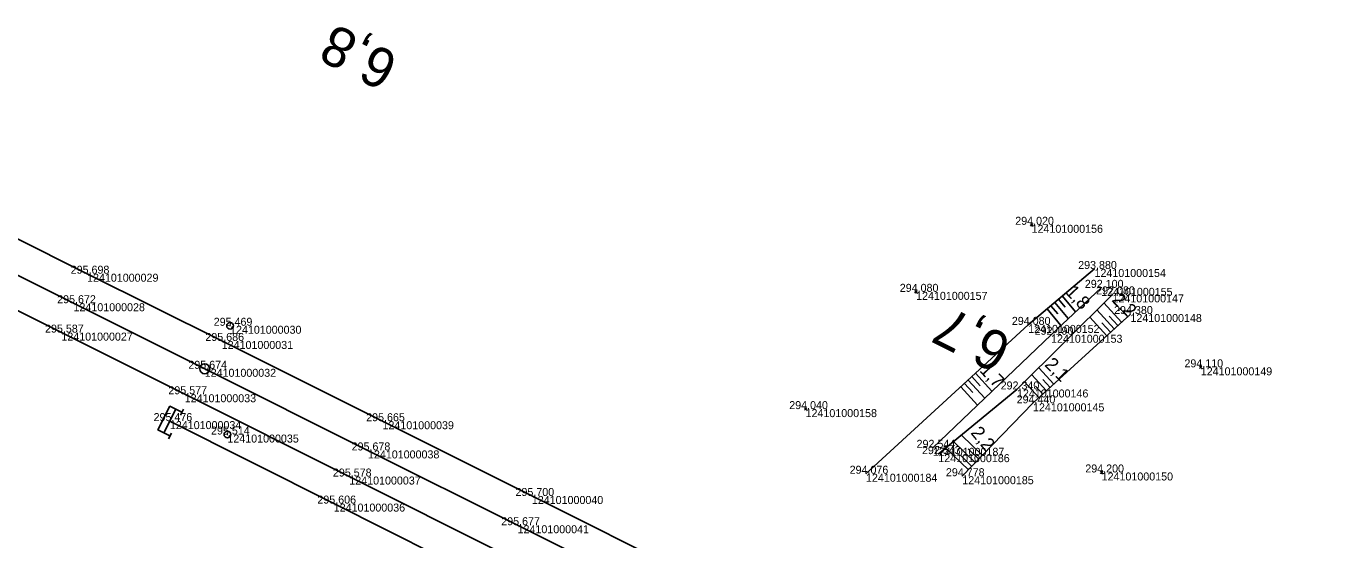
# Model space of a CAD drawing. Extents: x -616949 to -607976, y -1164436 to -1159224.
# Drawn here: x -613176.1 to -612978.5, y -1161592 to -1161515 of the extents above; entities that cross this region are included whole.
import ezdxf

# ---------------------------------------------------------------- set-up
doc = ezdxf.new("R2010")
doc.units = 0
for name, color, linetype in [('Vrstva 1', 7, 'Continuous'), ('Vrstva 15', 7, 'Continuous'), ('Vrstva 48', 7, 'Continuous'), ('Vrstva 49', 7, 'Continuous'), ('Vrstva 53', 7, 'Continuous'), ('Vrstva 60', 7, 'Continuous'), ('Vrstva 61', 7, 'Continuous'), ('Vrstva 7', 7, 'Continuous')]:
    doc.layers.add(name, color=color, linetype=linetype)

msp = doc.modelspace()

# ---------------------------------------------------------------- linework, layer by layer
at = {"layer": 'Vrstva 1'}
for points in [[(-612836.3, -1161723.7), (-612837.64, -1161723.01), (-612851, -1161716.12), (-612864.8, -1161706.96), (-612874.11, -1161700.74), (-612883.8, -1161694.67), (-612893.99, -1161688.92), (-612900.94, -1161685.35), (-612902.32, -1161684.67), (-612923.96, -1161673.82), (-612946.7, -1161662.43), (-612968.71, -1161651.4), (-612992.18, -1161639.63), (-613014.55, -1161628.42), (-613038.93, -1161616.22), (-613057.44, -1161606.93), (-613076.92, -1161597.16), (-613100.26, -1161585.47), (-613122.66, -1161574.25), (-613146.78, -1161562.2), (-613166.98, -1161552.11), (-613189.63, -1161540.79)], [(-612836.3, -1161723.7), (-612837.64, -1161723.01), (-612851, -1161716.12), (-612865.7, -1161708.54), (-612879.87, -1161701.29), (-612896.11, -1161693.08), (-612897.16, -1161692.56), (-612899.6, -1161691.36), (-612902.62, -1161689.84), (-612904.01, -1161689.16), (-612926.34, -1161677.97), (-612949.01, -1161666.64), (-612970.85, -1161655.69), (-612994.2, -1161644.02), (-613016.8, -1161632.71), (-613041.11, -1161620.53), (-613059.39, -1161611.38), (-613079.39, -1161601.37), (-613102.4, -1161589.86), (-613124.84, -1161578.63), (-613149.33, -1161566.38), (-613169.01, -1161556.54), (-613191.83, -1161545.12)], [(-612838.4, -1161727.97), (-612839.52, -1161727.39), (-612849.62, -1161722.19), (-612861.87, -1161715.89), (-612876.82, -1161708.21), (-612890.37, -1161701.36), (-612894.8, -1161699.12), (-612896.29, -1161698.37), (-612899.37, -1161696.83), (-612901.81, -1161695.62), (-612928.78, -1161682.13), (-612951.31, -1161670.85), (-612973.15, -1161659.9), (-612996.39, -1161648.28), (-613019.15, -1161636.88), (-613042.98, -1161624.98), (-613061.36, -1161615.73), (-613081.95, -1161605.44), (-613104.41, -1161594.19), (-613127.64, -1161582.55), (-613152.33, -1161570.2), (-613170.83, -1161560.95), (-613193.86, -1161549.42)], [(-612838.4, -1161727.97), (-612839.52, -1161727.39), (-612849.62, -1161722.19), (-612862.62, -1161717.56), (-612874.04, -1161713.43), (-612884.82, -1161709.14), (-612890.21, -1161706.69), (-612892.64, -1161705.54), (-612895.15, -1161704.3), (-612918.74, -1161692.45), (-613021.43, -1161641.02), (-613045.3, -1161629.07), (-613063.44, -1161619.97), (-613084.1, -1161609.63), (-613106.49, -1161598.41), (-613129.98, -1161586.61), (-613154.55, -1161574.23)]]:
    msp.add_lwpolyline(points, dxfattribs=at)
at = {"layer": 'Vrstva 15'}
for p, q in [((-613155.45, -1161576.01), (-613153.64, -1161572.44)), ((-613152.98, -1161573.34), (-613152.53, -1161572.45)), ((-613154.78, -1161576.91), (-613154.33, -1161576.02))]:
    msp.add_line(p, q, dxfattribs=at)
msp.add_lwpolyline([(-613152.75, -1161572.89), (-613154.54, -1161571.99), (-613156.34, -1161575.56), (-613154.55, -1161576.46)], dxfattribs=at)
at = {"layer": 'Vrstva 48'}
for p, q in [((-613021.83, -1161556.43), (-613019.79, -1161558.85)), ((-613021.26, -1161555.95), (-613020.25, -1161557.14)), ((-613020.68, -1161555.47), (-613018.7, -1161557.82)), ((-613011.8, -1161559.38), (-613014.45, -1161556.5)), ((-613022.98, -1161557.4), (-613020.89, -1161559.88)), ((-613022.4, -1161556.92), (-613021.37, -1161558.14)), ((-613014.02, -1161561.41), (-613016.58, -1161558.61)), ((-613012.91, -1161560.4), (-613015.52, -1161557.55)), ((-613012.36, -1161559.89), (-613013.67, -1161558.46)), ((-613013.46, -1161560.9), (-613014.76, -1161559.49)), ((-613021.96, -1161568.69), (-613024.22, -1161566.22)), ((-613035.38, -1161568.58), (-613034.12, -1161569.95)), ((-613034.83, -1161568.07), (-613032.33, -1161570.8)), ((-613034.28, -1161567.56), (-613033.03, -1161568.92)), ((-613033.72, -1161567.06), (-613031.24, -1161569.76)), ((-613024.17, -1161570.72), (-613026.35, -1161568.34)), ((-613023.07, -1161569.7), (-613025.28, -1161567.28)), ((-613022.51, -1161569.2), (-613023.63, -1161567.98)), ((-613035.93, -1161569.09), (-613033.41, -1161571.83)), ((-613023.62, -1161570.21), (-613024.72, -1161569.01)), ((-613032.68, -1161579.4), (-613035.83, -1161576.35)), ((-613034.77, -1161581.55), (-613038.16, -1161578.27)), ((-613033.73, -1161580.48), (-613037, -1161577.31)), ((-613033.21, -1161579.94), (-613034.81, -1161578.38)), ((-613034.25, -1161581.02), (-613035.92, -1161579.4))]:
    msp.add_line(p, q, dxfattribs=at)
at = {"layer": 'Vrstva 49'}
for p, q in [((-613025.48, -1161544.59), (-613025.12, -1161544.95)), ((-613025.48, -1161544.95), (-613025.12, -1161544.59)), ((-613025.81, -1161559.79), (-613015.86, -1161551.4)), ((-613042.8, -1161554.65), (-613042.44, -1161555.01)), ((-613042.8, -1161555.01), (-613042.44, -1161554.65)), ((-613022.38, -1161561.27), (-613014.86, -1161554.23)), ((-613027.49, -1161569.48), (-613013.16, -1161555.21)), ((-613025.09, -1161571.56), (-613010.47, -1161558.16)), ((-613025.81, -1161559.79), (-613050.14, -1161582.13)), ((-613040.1, -1161578.24), (-613022.38, -1161561.27)), ((-613000.1, -1161565.98), (-612999.74, -1161566.34)), ((-613000.1, -1161566.34), (-612999.74, -1161565.98)), ((-613027.49, -1161569.48), (-613039.29, -1161579.19)), ((-613059.38, -1161572.25), (-613059.02, -1161572.61)), ((-613059.38, -1161572.61), (-613059.02, -1161572.25)), ((-613035.69, -1161582.5), (-613025.09, -1161571.56)), ((-613014.97, -1161581.76), (-613014.61, -1161582.12)), ((-613014.97, -1161582.12), (-613014.61, -1161581.76))]:
    msp.add_line(p, q, dxfattribs=at)
at = {"layer": 'Vrstva 53'}
msp.add_line((-613145.98, -1161576.25), (-613145.88, -1161576.25), dxfattribs=at)
msp.add_circle((-613145.93, -1161576.25), 0.499, dxfattribs=at)
at = {"layer": 'Vrstva 60'}
for p, q in [((-613025.3, -1161544.77), (-613025.3, -1161544.77)), ((-613166.98, -1161552.11), (-613166.98, -1161552.11)), ((-613015.86, -1161551.4), (-613015.86, -1161551.4)), ((-613042.62, -1161554.83), (-613042.62, -1161554.83)), ((-613014.86, -1161554.23), (-613014.86, -1161554.23)), ((-613169.01, -1161556.54), (-613169.01, -1161556.54)), ((-613013.16, -1161555.21), (-613013.16, -1161555.21)), ((-613010.47, -1161558.16), (-613010.47, -1161558.16)), ((-613145.53, -1161559.92), (-613145.53, -1161559.92)), ((-613025.81, -1161559.79), (-613025.81, -1161559.79)), ((-613170.83, -1161560.95), (-613170.83, -1161560.95)), ((-613146.78, -1161562.2), (-613146.78, -1161562.2)), ((-613022.38, -1161561.27), (-613022.38, -1161561.27)), ((-613149.33, -1161566.38), (-613149.33, -1161566.38)), ((-612999.92, -1161566.16), (-612999.92, -1161566.16)), ((-613152.33, -1161570.2), (-613152.33, -1161570.2)), ((-613027.49, -1161569.48), (-613027.49, -1161569.48)), ((-613059.2, -1161572.43), (-613059.2, -1161572.43)), ((-613025.09, -1161571.56), (-613025.09, -1161571.56)), ((-613154.55, -1161574.23), (-613154.55, -1161574.23)), ((-613122.66, -1161574.25), (-613122.66, -1161574.25)), ((-613145.93, -1161576.25), (-613145.93, -1161576.25)), ((-613040.1, -1161578.24), (-613040.1, -1161578.24)), ((-613124.84, -1161578.63), (-613124.84, -1161578.63)), ((-613039.29, -1161579.19), (-613039.29, -1161579.19)), ((-613050.14, -1161582.13), (-613050.14, -1161582.13)), ((-613014.79, -1161581.94), (-613014.79, -1161581.94)), ((-613127.64, -1161582.55), (-613127.64, -1161582.55)), ((-613035.69, -1161582.5), (-613035.69, -1161582.5)), ((-613100.26, -1161585.47), (-613100.26, -1161585.47)), ((-613129.98, -1161586.61), (-613129.98, -1161586.61)), ((-613102.4, -1161589.86), (-613102.4, -1161589.86))]:
    msp.add_line(p, q, dxfattribs=at)
at = {"layer": 'Vrstva 7'}
msp.add_line((-613145.48, -1161559.94), (-613145.57, -1161559.89), dxfattribs=at)
for centre, radius in [((-613145.53, -1161559.92), 0.5), ((-613149.33, -1161566.38), 0.75)]:
    msp.add_circle(centre, radius, dxfattribs=at)

# ---------------------------------------------------------------- texts
at = {"layer": 'Vrstva 48'}
for s, rotation, p in [('1,8', 313.1118, (-613020.33, -1161554.94)), ('2,2', 314.8798, (-613013.39, -1161556.15)), ('1,7', 313.7681, (-613033.21, -1161566.71)), ('2,1', 314.8798, (-613023.46, -1161565.86)), ('2,2', 309.4685, (-613034.52, -1161576.03))]:
    msp.add_text(s, height=2, rotation=rotation, dxfattribs=at).set_placement(p)
at = {"layer": 'Vrstva 60'}
for s, p in [('124101000156', (-613025.3, -1161545.97)), ('124101000029', (-613166.98, -1161553.31)), ('124101000154', (-613015.86, -1161552.6)), ('124101000157', (-613042.62, -1161556.03)), ('124101000155', (-613014.86, -1161555.43)), ('124101000028', (-613169.01, -1161557.74)), ('124101000147', (-613013.16, -1161556.41)), ('124101000148', (-613010.47, -1161559.36)), ('124101000030', (-613145.53, -1161561.12)), ('124101000152', (-613025.81, -1161560.99)), ('124101000027', (-613170.83, -1161562.15)), ('124101000031', (-613146.78, -1161563.4)), ('124101000153', (-613022.38, -1161562.47)), ('124101000032', (-613149.33, -1161567.58)), ('124101000149', (-612999.92, -1161567.36)), ('124101000033', (-613152.33, -1161571.4)), ('124101000146', (-613027.49, -1161570.68)), ('124101000158', (-613059.2, -1161573.63)), ('124101000145', (-613025.09, -1161572.76)), ('124101000034', (-613154.55, -1161575.43)), ('124101000039', (-613122.66, -1161575.45)), ('124101000035', (-613145.93, -1161577.45)), ('124101000187', (-613040.1, -1161579.44)), ('124101000038', (-613124.84, -1161579.83)), ('124101000186', (-613039.29, -1161580.39)), ('124101000184', (-613050.14, -1161583.33)), ('124101000185', (-613035.69, -1161583.7)), ('124101000150', (-613014.79, -1161583.14)), ('124101000037', (-613127.64, -1161583.75)), ('124101000040', (-613100.26, -1161586.67)), ('124101000036', (-613129.98, -1161587.81)), ('124101000041', (-613102.4, -1161591.06))]:
    msp.add_text(s, height=1.2, dxfattribs=at).set_placement(p)
at = {"layer": 'Vrstva 61'}
for s, p in [('294.020', (-613027.75, -1161544.77)), ('293.880', (-613018.31, -1161551.4)), ('295.698', (-613169.43, -1161552.11)), ('294.080', (-613045.07, -1161554.83)), ('292.100', (-613017.31, -1161554.23)), ('292.080', (-613015.61, -1161555.21)), ('295.672', (-613171.46, -1161556.54)), ('295.469', (-613147.98, -1161559.92)), ('294.080', (-613028.26, -1161559.79)), ('294.380', (-613012.92, -1161558.16)), ('295.587', (-613173.28, -1161560.95)), ('292.190', (-613024.83, -1161561.27)), ('295.686', (-613149.23, -1161562.2)), ('295.674', (-613151.78, -1161566.38)), ('294.110', (-613002.37, -1161566.16)), ('292.340', (-613029.94, -1161569.48)), ('295.577', (-613154.78, -1161570.2)), ('294.440', (-613027.54, -1161571.56)), ('294.040', (-613061.65, -1161572.43)), ('295.476', (-613157, -1161574.23)), ('295.665', (-613125.11, -1161574.25)), ('295.514', (-613148.38, -1161576.25)), ('295.678', (-613127.29, -1161578.63)), ('292.544', (-613042.55, -1161578.24)), ('292.543', (-613041.74, -1161579.19)), ('295.578', (-613130.1, -1161582.55)), ('294.076', (-613052.59, -1161582.13)), ('294.778', (-613038.15, -1161582.5)), ('294.200', (-613017.24, -1161581.94)), ('295.700', (-613102.71, -1161585.47)), ('295.606', (-613132.43, -1161586.61)), ('295.677', (-613104.85, -1161589.86))]:
    msp.add_text(s, height=1.2, dxfattribs=at).set_placement(p)
at = {"layer": 'Vrstva 7'}
for s, rotation, p in [('6,8', 153.4303, (-613119.96, -1161519.46)), ('6,7', 153.3961, (-613027.94, -1161561.82))]:
    msp.add_text(s, height=6, rotation=rotation, dxfattribs=at).set_placement(p)

doc.saveas('drawing.dxf')
